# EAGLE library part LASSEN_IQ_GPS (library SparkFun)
Lassen iq 12-Channel GPS receiver. Schematic and footprint production proven. Spark Fun Electronics SKU : GPS-IQ. Surface mount mating connector : Connector-IQ-SMD
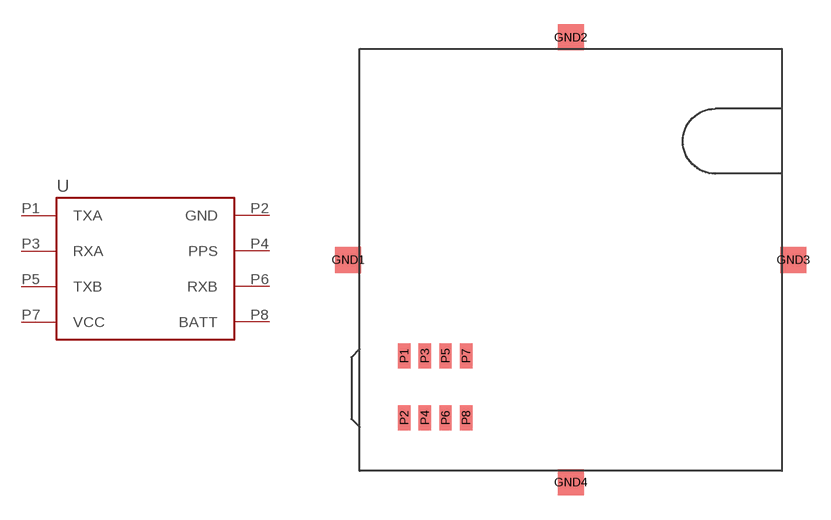
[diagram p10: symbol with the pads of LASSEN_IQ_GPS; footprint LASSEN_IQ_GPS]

Designator prefix -

## LASSEN_IQ_GPS  [LASSEN_IQ_GPS]
P1  TXA
P2  GND  pwr
P3  RXA
P4  PPS
P5  TXB
P6  RXB
P7  VCC  pwr
P8  BATT

## Footprint LASSEN_IQ_GPS (pad centres in mm)
smd 1.6 x 1.6: GND1 -0.7,13; GND2 13,26.7; GND3 26.7,13; GND4 13,-0.7
smd 0.762 x 1.524: P1 2.752,7.076; P2 2.752,3.266; P3 4.022,7.076; P4 4.022,3.266; P5 5.292,7.076; P6 5.292,3.266; P7 6.562,7.076; P8 6.562,3.266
